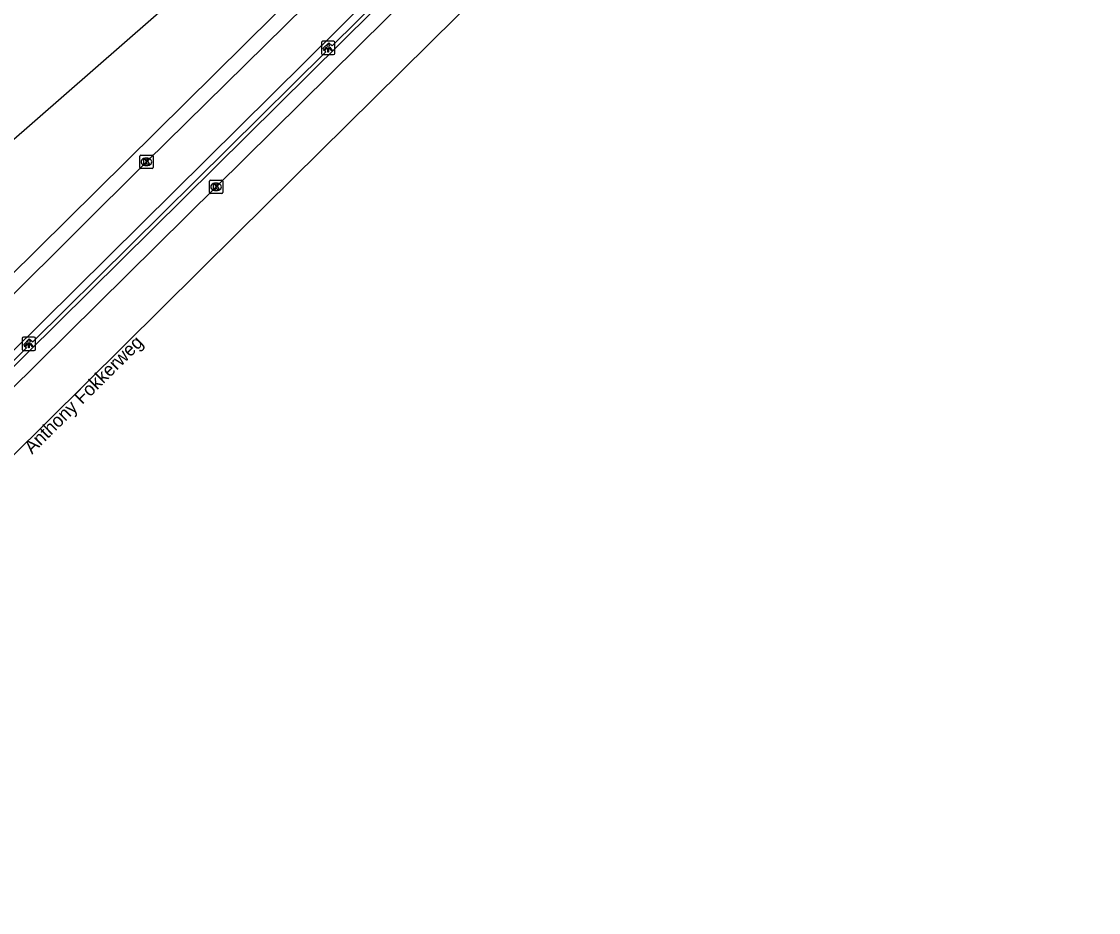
# Model space of a CAD drawing. Extents: x 157321 to 158827, y 386650 to 388532.
# Drawn here: x 158165.7 to 158246.4, y 386652.2 to 386718.9 of the extents above; entities that cross this region are included whole.
import ezdxf

# ---------------------------------------------------------------- set-up
doc = ezdxf.new("R2010")
doc.units = 0
for name, color, linetype in [('IMGEO_Fietspad_gesloten', 7, 'Continuous'), ('IMGEO_Groenvoorziening', 7, 'Continuous'), ('IMGEO_Kolk', 7, 'Continuous'), ('IMGEO_Lichtpunt', 7, 'Continuous'), ('IMGEO_Muur', 7, 'Continuous'), ('IMGEO_Openbare_ruimte_label', 7, 'Continuous'), ('IMGEO_Rijbaan_regionaal_gesloten', 7, 'Continuous'), ('IMGEO_Voetpad_open', 7, 'Continuous')]:
    doc.layers.add(name, color=color, linetype=linetype)

msp = doc.modelspace()

# ---------------------------------------------------------------- linework, layer by layer
at = {"layer": 'IMGEO_Fietspad_gesloten'}
for points in [[(158246.514, 386779.103), (158228.231, 386760.992), (158217.135, 386750), (158209.913, 386742.846), (158192.844, 386725.961), (158175.027, 386708.422), (158159.233, 386692.731), (158145.663, 386679.284), (158145.425, 386679.048), (158142.102, 386675.756), (158141.033, 386674.697), (158136.681, 386670.385), (158135.683, 386669.396), (158135.611, 386669.325), (158133.839, 386667.573), (158132.768, 386666.514), (158128.07, 386661.871), (158126.998, 386660.812), (158125.081, 386658.917)], [(158126.956, 386656.62), (158128.881, 386658.524), (158129.952, 386659.584), (158134.654, 386664.236), (158135.725, 386665.295), (158137.494, 386667.046), (158138.564, 386668.105), (158142.919, 386672.413), (158143.989, 386673.472), (158147.313, 386676.761), (158147.552, 386676.997), (158221.341, 386750), (158230.147, 386758.713), (158239.292, 386767.76)]]:
    msp.add_lwpolyline(points, dxfattribs=at)
at = {"layer": 'IMGEO_Groenvoorziening'}
msp.add_lwpolyline([(158156.923, 386701.791), (158157.948, 386703.907), (158210.728, 386750), (158225.895, 386763.769), (158231.903, 386769.223), (158238.792, 386774.559)], dxfattribs=at)
at = {"layer": 'IMGEO_Kolk'}
for p, q in [((158174.524, 386707.997), (158174.524, 386708.849)), ((158174.599, 386708.923), (158175.451, 386708.923)), ((158175.012, 386708.703), (158175.037, 386708.703)), ((158175.525, 386708.849), (158175.525, 386707.997)), ((158175.451, 386707.923), (158174.599, 386707.923)), ((158175.035, 386708.143), (158175.01, 386708.143)), ((158179.743, 386706.125), (158179.743, 386706.977)), ((158179.818, 386707.051), (158180.67, 386707.051)), ((158180.231, 386706.831), (158180.256, 386706.831)), ((158180.744, 386706.977), (158180.744, 386706.125)), ((158180.67, 386706.051), (158179.818, 386706.051)), ((158180.254, 386706.271), (158180.229, 386706.271))]:
    msp.add_line(p, q, dxfattribs=at)
for points in [[(158174.524, 386707.997), (158174.524, 386708.849)], [(158174.599, 386708.923), (158175.451, 386708.923)], [(158174.845, 386708.623), (158174.968, 386708.623), (158174.968, 386708.472), (158175.098, 386708.623), (158175.262, 386708.623), (158175.116, 386708.472), (158175.269, 386708.223), (158175.117, 386708.223), (158175.032, 386708.387), (158174.968, 386708.32), (158174.968, 386708.223), (158174.845, 386708.223), (158174.845, 386708.623)], [(158175.525, 386708.849), (158175.525, 386707.997)], [(158175.451, 386707.923), (158174.599, 386707.923)], [(158179.743, 386706.125), (158179.743, 386706.977)], [(158179.818, 386707.051), (158180.67, 386707.051)], [(158180.744, 386706.977), (158180.744, 386706.125)], [(158180.67, 386706.051), (158179.818, 386706.051)], [(158180.064, 386706.751), (158180.187, 386706.751), (158180.187, 386706.6), (158180.317, 386706.751), (158180.481, 386706.751), (158180.335, 386706.6), (158180.488, 386706.351), (158180.336, 386706.351), (158180.251, 386706.515), (158180.187, 386706.448), (158180.187, 386706.351), (158180.064, 386706.351), (158180.064, 386706.751)]]:
    msp.add_lwpolyline(points, dxfattribs=at)
for centre, start, end in [((158174.601, 386708.847), 91.55205, 178.44795), ((158174.601, 386708.847), 91.55205, 178.44795), ((158175.449, 386708.847), 1.55205, 88.44795), ((158175.449, 386708.847), 1.55205, 88.44795), ((158174.601, 386707.999), 181.55205, 268.44795), ((158174.601, 386707.999), 181.55205, 268.44795), ((158175.449, 386707.999), 271.55205, 358.44795), ((158175.449, 386707.999), 271.55205, 358.44795), ((158179.82, 386706.975), 91.55205, 178.44795), ((158179.82, 386706.975), 91.55205, 178.44795), ((158180.668, 386706.975), 1.55205, 88.44795), ((158180.668, 386706.975), 1.55205, 88.44795), ((158179.82, 386706.127), 181.55205, 268.44795), ((158179.82, 386706.127), 181.55205, 268.44795), ((158180.668, 386706.127), 271.55205, 358.44795), ((158180.668, 386706.127), 271.55205, 358.44795)]:
    msp.add_arc(centre, 0.0765, start, end, dxfattribs=at)
for centre, major_axis, ratio, start_param, end_param in [((158175.011, 386708.423), (-0.387, 0.002), 0.722429, 4.712389, 7.853982), ((158175.036, 386708.423), (-0.39, 0.002), 0.717154, 1.570796, 4.712389), ((158180.23, 386706.551), (-0.387, 0.002), 0.722429, 4.712389, 7.853982), ((158180.255, 386706.551), (-0.39, 0.002), 0.717154, 1.570796, 4.712389)]:
    msp.add_ellipse(centre, major_axis=major_axis, ratio=ratio, start_param=start_param, end_param=end_param, dxfattribs=at)
at = {"layer": 'IMGEO_Lichtpunt'}
for p, q in [((158188.141, 386717.355), (158188.141, 386716.548)), ((158188.141, 386717.355), (158188.141, 386716.548)), ((158189.043, 386717.45), (158188.235, 386717.45)), ((158189.043, 386717.45), (158188.235, 386717.45)), ((158189.137, 386716.548), (158189.137, 386717.355)), ((158189.137, 386716.548), (158189.137, 386717.355)), ((158188.235, 386716.454), (158189.043, 386716.454)), ((158188.235, 386716.454), (158189.043, 386716.454)), ((158165.718, 386695.192), (158165.718, 386694.385)), ((158165.718, 386695.192), (158165.718, 386694.385)), ((158166.62, 386695.287), (158165.812, 386695.287)), ((158166.62, 386695.287), (158165.812, 386695.287)), ((158166.714, 386694.385), (158166.714, 386695.192)), ((158166.714, 386694.385), (158166.714, 386695.192)), ((158165.812, 386694.291), (158166.62, 386694.291)), ((158165.812, 386694.291), (158166.62, 386694.291))]:
    msp.add_line(p, q, dxfattribs=at)
for points in [[(158188.515, 386717.019), (158188.554, 386716.991), (158188.366, 386716.729), (158188.328, 386716.756), (158188.515, 386717.019)], [(158188.617, 386716.971), (158188.664, 386716.971), (158188.664, 386716.649), (158188.617, 386716.649), (158188.617, 386716.971)], [(158188.727, 386716.991), (158188.765, 386717.018), (158188.952, 386716.756), (158188.913, 386716.728), (158188.727, 386716.991)], [(158166.092, 386694.856), (158166.131, 386694.828), (158165.943, 386694.566), (158165.905, 386694.593), (158166.092, 386694.856)], [(158166.194, 386694.808), (158166.241, 386694.808), (158166.241, 386694.486), (158166.194, 386694.486), (158166.194, 386694.808)], [(158166.304, 386694.828), (158166.342, 386694.855), (158166.529, 386694.593), (158166.49, 386694.565), (158166.304, 386694.828)]]:
    msp.add_lwpolyline(points, dxfattribs=at)
for centre in [(158188.64, 386717.153), (158166.217, 386694.99)]:
    msp.add_circle(centre, 0.0994, dxfattribs=at)
for centre, start, end in [((158188.235, 386717.355), 90, 180), ((158188.235, 386717.355), 90, 180), ((158189.043, 386717.355), 0, 90), ((158189.043, 386717.355), 0, 90), ((158188.235, 386716.548), 180, 270), ((158188.235, 386716.548), 180, 270), ((158189.043, 386716.548), 270, 0), ((158189.043, 386716.548), 270, 360), ((158165.812, 386695.192), 90, 180), ((158165.812, 386695.192), 90, 180), ((158166.62, 386695.192), 0, 90), ((158166.62, 386695.192), 0, 90), ((158165.812, 386694.385), 180, 270), ((158165.812, 386694.385), 180, 270), ((158166.62, 386694.385), 270, 0), ((158166.62, 386694.385), 270, 360)]:
    msp.add_arc(centre, 0.0946, start, end, dxfattribs=at)
at = {"layer": 'IMGEO_Muur'}
for points in [[(158151.906, 386680.081), (158222.586, 386750), (158230.713, 386758.04), (158239.93, 386767.157), (158239.715, 386767.353)], [(158147.899, 386676.576), (158166.051, 386694.498), (158165.831, 386694.748), (158166.252, 386695.177), (158166.505, 386694.938), (158188.48, 386716.669), (158188.255, 386716.916), (158188.683, 386717.348), (158188.935, 386717.101), (158210.909, 386738.797)]]:
    msp.add_lwpolyline(points, dxfattribs=at)
at = {"layer": 'IMGEO_Rijbaan_regionaal_gesloten'}
for points in [[(158130.556, 386652.21), (158151.056, 386672.76), (158161.945, 386683.393), (158181.844, 386703.082), (158200.321, 386721.363), (158241.47, 386762.076), (158261.924, 386782.315), (158286.694, 386806.822), (158320.475, 386840.246), (158335.714, 386855.078), (158347.338, 386866.652)], [(158248.295, 386773.884), (158232.079, 386757.861), (158231.417, 386757.203), (158224.159, 386750), (158214.351, 386740.265), (158197.287, 386723.414), (158180.244, 386706.55), (158162.477, 386688.992), (158152.593, 386679.247)]]:
    msp.add_lwpolyline(points, dxfattribs=at)
at = {"layer": 'IMGEO_Voetpad_open'}
msp.add_lwpolyline([(158245.735, 386779.893), (158227.5, 386761.861), (158215.506, 386750), (158164.686, 386699.745)], dxfattribs=at)

# ---------------------------------------------------------------- texts
at = {"layer": 'IMGEO_Openbare_ruimte_label'}
msp.add_text('Anthony Fokkerweg', height=1, rotation=44.67584, dxfattribs=at).set_placement((158166.455, 386686.492))

doc.saveas('drawing.dxf')
